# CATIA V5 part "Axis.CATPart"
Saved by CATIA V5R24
Part number: Axis
Material "Steel": density 7860 kg/m3, Young's modulus 2e+11 Pa, Poisson ratio 0.266, thermal expansion 1.17e-05 1/K
Bounding box of the stored display mesh (mm): x -8.5 to 8.5, y -21.55 to -20.45, z 0.85 to 1.95
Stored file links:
  C:\Users\Jules\Documents\ECL\Watch\Axis.CATPart
  C:\Users\Jules\Documents\ECL\Watch\Side link.CATPart
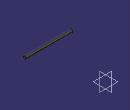
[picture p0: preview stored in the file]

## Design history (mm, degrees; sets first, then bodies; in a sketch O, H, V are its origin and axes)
Body1 (main body)
  DatumSurface1
  Sketch1 on yz-plane, origin (0, 0, 0), H (0, 1, 0), V (0, 0, 1)
    construction line L1 (-24, 2.8) -> (-21, 2.8)
    construction arc A1 centre (-21, 1.4) radius 1.4 from (-21, 2.8) to (-21, 0) cw
    point P3 (-21, 1.4)
    point P4 (-21, 0)
    construction line L2 (-21, 0) -> (-24, 0)
    construction arc A2 centre (-24, 1.4) radius 1.4 from (-24, 0) to (-24, 2.8) cw
    circle A3 centre (-21, 1.4) radius 0.55
    construction circle A4 centre (-24, 1.4) radius 0.55
    radius A1 = 1.4
    length L2 = 3
    distance P3 V = 21
    radius A3 = 0.55
    radius A4 = 0.55
    horizontal: L1 H
    coincidence: P4 H
    tangency: A1 L1, L2 A1, A2 L1, A2 L2
  Pad1: profile Sketch1, direction (1, 0, 0), length 8.5, mirrored extent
